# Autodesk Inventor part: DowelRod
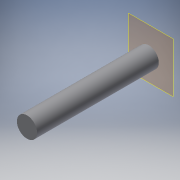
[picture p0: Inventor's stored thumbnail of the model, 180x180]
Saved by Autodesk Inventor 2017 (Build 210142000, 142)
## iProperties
Created: 2017-04
Part Number: DowelRod
Material: Generic
Document SubType Name: Modeling
Designer: 1460374
Density: 1 g/cm^3
Appearance: Default
Author: 1460374
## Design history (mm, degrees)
workplane "Work Plane1"
sketch "Sketch1"
  geometry: C1 r 3.675 at (-20.832, -32.731) reference; C2 r 3.175 at (-15.525, -11.469); 1 further point
  constraints: 1 centre point
  dimensions: "d0" = 6.35 diameter of C2
extrude "Extrusion1" new body sketch "Sketch1" distance "d1" = 38.1; taper "d2" = 0 deg
sketch "Sketch2"
  geometry: C1 r 3.175 at (0, 0) reference; C2 r 3.175 at (0, 0); 1 further point
  constraints: 1 centre point, 1 coincident
workplane "Work Plane2"
extrude "Extrusion2" join sketch "Sketch2" stored distance "d3" = 38.1; taper "d4" = 0 deg
body "Solid1"
node "Reference1"
